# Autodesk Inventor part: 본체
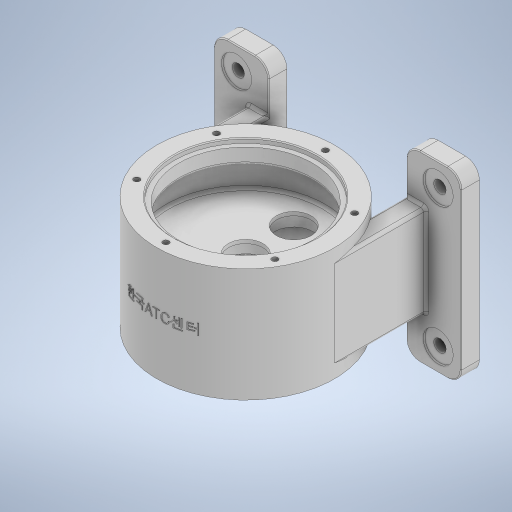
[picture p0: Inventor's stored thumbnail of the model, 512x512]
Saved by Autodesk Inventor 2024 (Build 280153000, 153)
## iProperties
Created: 2025-12
Part Number: 본체
Material: 일반
Document SubType Name: Modeling
Designer: Edu07
Density: 1 g/cm^3
Appearance: 기본값
Author: Edu07
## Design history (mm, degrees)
sketch "스케치3"
  geometry: L1 (135, 85)-(135, -85); L2 (-135, -85)-(-135, 85); L3 (-75, -85)-(-75, 85); L4 (75, 85)-(75, -85); L5 (-120, 100)-(-90, 100); L6 (90, 100)-(120, 100); L7 (120, -100)-(90, -100); L8 (-90, -100)-(-120, -100); C1 r 6.75 at (-110, 75); C2 r 6.75 at (110, 75); C3 r 6.75 at (110, -75); C4 r 6.75 at (-110, -75); A1 r 15 centre (-120, 85) between (-120, 100) and (-135, 85); A2 r 15 centre (-90, 85) between (-75, 85) and (-90, 100); A3 r 15 centre (-90, -85) between (-90, -100) and (-75, -85); A4 r 15 centre (-120, -85) between (-135, -85) and (-120, -100); A5 r 15 centre (90, 85) between (90, 100) and (75, 85); A6 r 15 centre (120, 85) between (135, 85) and (120, 100); A7 r 15 centre (120, -85) between (120, -100) and (135, -85); A8 r 15 centre (90, -85) between (75, -85) and (90, -100); 3 further points
  constraints: 16 end point, 16 point on circle, 16 tangent, 12 centre point, 7 equal radius, 7 parallel, 4 point on line, 2 perpendicular
  dimensions: "d4" = 200 distance of point (135, 100) point (135, -100); "d5" = 60 distance between parallel lines of L2 L3; "d6" = 60 distance between parallel lines of L1 L4; "d7" = 15 radius of A1; "d10" = 13.5 diameter of C1; "d11" = 13.5 diameter of C2; "d12" = 13.5 diameter of C3; "d13" = 13.5 diameter of C4
extrude "돌출3" new body sketch "스케치3" distance "d16" = 20; taper "d17" = 0 deg
sketch "스케치4"
  geometry: C1 r 6.75 at (-110, 75) reference; C2 r 16.5 at (-110, 75); C3 r 6.75 at (-110, -75) reference; C4 r 16.5 at (-110, -75); C5 r 6.75 at (110, 75) reference; C6 r 16.5 at (110, 75); C7 r 6.75 at (110, -75) reference; C8 r 16.5 at (110, -75); 1 further point
  constraints: 4 centre point, 4 coincident
  dimensions: "d18" = 33 diameter of C2; "d19" = 33 diameter of C4; "d20" = 33 diameter of C6; "d21" = 33 diameter of C8
extrude "돌출4" cut sketch "스케치4" distance "d22" = 2; taper "d23" = 0 deg
sketch "스케치6"
  geometry: L1 (0, 0)-(0, 120); C1 r 97 at (0, 120)
  constraints: 2 end point, 1 centre point, 1 coincident, 1 vertical
  dimensions: "d24" = 120 distance of L1.start L1.end; "d25" = 194 diameter of C1
extrude "돌출5" join sketch "스케치6" stored distance "d26" = 124; taper "d27" = 0 deg
node "작업 평면2"
sketch "스케치7"
  geometry: 2 further points
  constraints: 2 coincident, 1 other
feature "엠보싱1" sketch "스케치7" dims "d4" = 200, "d5" = 60, "d6" = 60, "d7" = 15, "d29" = 0.5, "d30" = 0
sketch "스케치9"
  geometry: L1 (75, 20)-(75, 58.486) reference; L2 (75, 0)-(75, 20) reference; L3 (75, 20)-(97, 20); L4 (120, 20)-(90, 20) reference; L5 (97, 20)-(97, 120); L6 (75, 20)-(75, 58.486); A1 r 97 centre (0, 120) between (75, 58.486) and (97, 120) reference; A2 r 97 centre (0, 120) between (75, 58.486) and (97, 120); 1 further point
  constraints: 6 end point, 3 point on circle, 1 centre point, 1 collinear, 1 concentric, 1 perpendicular, 1 point on line
  dimensions: "d38" = 22 distance of L1.start L3.end
extrude "돌출6" join sketch "스케치9" stored distance "d39" = 100; taper "d40" = 0 deg
sketch "스케치10"
  geometry: C1 r 78 at (0, 0); 1 further point
  constraints: 1 centre point
  dimensions: "d43" = 156 diameter of C1
extrude "돌출7" cut sketch "스케치10" distance "d44" = 5; taper "d45" = 0 deg
sketch "스케치11"
  geometry: C1 r 78 at (0, 0) reference; C2 r 73 at (0, 0); 1 further point
  constraints: 1 centre point, 1 coincident
  dimensions: "d46" = 146 diameter of C2
  node "투영된 루프2"
sketch "스케치12"
  geometry: 1 further point
extrude "돌출8" cut sketch "스케치11" distance "d47" = 17; taper "d48" = 0 deg
sketch "스케치13"
  geometry: C1 r 73 at (0, 0) reference; C2 r 87 at (0, 0); 1 further point
  constraints: 1 centre point, 1 coincident
  dimensions: "d49" = 174 diameter of C2
extrude "돌출9" cut sketch "스케치13" distance "d50" = 32; taper "d51" = 0 deg
sketch "스케치14"
  geometry: C1 r 73 at (0, 0) reference; C2 r 21 at (0, 0); 1 further point
  constraints: 1 centre point, 1 coincident
  dimensions: "d52" = 42 diameter of C2
extrude "돌출10" cut sketch "스케치14" distance "d53" = 12; taper "d54" = 0 deg
sketch "스케치15"
  geometry: C1 r 19 at (0, 0); 1 further point
  constraints: 1 centre point
  dimensions: "d55" = 38 diameter of C1
extrude "돌출11" cut sketch "스케치15" distance "d56" = 12; taper "d57" = 0 deg
sketch "스케치16" dims "d58" = 174
  geometry: 3 further points
  constraints: 1 vertical alignment, 2 other
hole "구멍1" sketch "스케치16" at (0, 87) diameter "d59" = 6.647; stored, may be unused: countersink angle "d63" = 82 deg, drill point angle "d65" = 118 deg; dims "d60" = 16, "d61" = 3.023, "d62" = 2, "d64" = 18
sketch "스케치19"
  geometry: L1 (75, 8)-(36.6, 30.17); L2 (75, 58.486)-(75, 20) reference; L3 (75, 8)-(75, 58.486); C1 r 3.324 at (75.344, 163.5) reference; C2 r 3.324 at (75.344, 76.5) reference; C3 r 3.324 at (0, 33) reference; C4 r 3.324 at (-75.344, 76.5) reference; C5 r 3.324 at (-75.344, 163.5) reference; C6 r 3.324 at (0, 207) reference; C7 r 78 at (0, 120) reference; A1 r 97 centre (0, 120) between (75, 58.486) and (36.6, 30.17) reference; 2 further points
  constraints: 4 end point, 2 point on circle
feature "리브2" sketch "스케치19" dims "d78" = 1, "d79" = 12, "d80" = 0, "d81" = 0, "d82" = 1, "d83" = 1
chamfer "모따기1" distance "d84" = 1; stored, may be unused: second distance "d85" = 2, angle "d86" = 30 deg
fillet "모깎기1" dims "d87" = 3
fillet "모깎기2" dims "d88" = 3
fillet "모깎기3" dims "d89" = 3
fillet "모깎기4" dims "d90" = 3
sketch "스케치20"
  geometry: 1 further point
sketch "스케치21"
  geometry: L1 (-57, 47)-(-57, 193) reference; L2 (-57, 193)-(-40, 193); L3 (-57, 193)-(-8, 193) reference; L4 (-40, 193)-(-8, 193); L5 (-8, 99)-(-8, 141) reference; L6 (-8, 207)-(-40, 207); L7 (-40, 207)-(-40, 193); L8 (-8, 120)-(-43.798, 120); L9 (-47, 120)-(47, 120) reference; L10 (-8, 207)-(-8, 193); 1 further point
  constraints: 12 end point, 3 point on line, 1 midpoint, 1 vertical
  dimensions: "d93" = 17 distance of L1.end L2.end; "d94" = 32 distance of L2.end L4.end; "d95" = 87 distance of L8.start L6.start; "d96" = 32 distance of L6.start L6.end
revolve "회전1" sketch "스케치21" stored, may be unused: angle "d97" = 90 deg
sketch "스케치22"
  geometry: 1 further point
fillet "모깎기5" dims "d98" = 3
fillet "모깎기6" dims "d99" = 3
chamfer "모따기2" distance "d100" = 1; stored, may be unused: second distance "d101" = 2, angle "d102" = 30 deg
chamfer "모따기3" distance "d103" = 1; stored, may be unused: second distance "d104" = 2, angle "d105" = 30 deg
sketch "스케치25"
  geometry: L1 (0, 0)-(0, 52.5); C1 r 19 at (0, 52.5); 1 further point
  constraints: 2 end point, 1 centre point, 1 coincident, 1 vertical
  dimensions: "d108" = 52.5 distance of L1.start L1.end; "d109" = 38 diameter of C1
extrude "돌출12" cut sketch "스케치25" distance "d110" = 4; taper "d111" = 0 deg
sketch "스케치26"
  geometry: C1 r 21 at (0, 0); 1 further point
  constraints: 1 centre point
  dimensions: "d112" = 42 diameter of C1
extrude "돌출13" cut sketch "스케치26" stored distance "d113" = 4; taper "d114" = 0 deg
sketch "스케치27"
  geometry: L1 (-23.383, -39)-(-35.599, -60.16); L2 (-39.648, -67.172)-(-40.933, -69.398); L3 (23.383, -39)-(35.599, -60.16); C1 r 21 at (0, -52.5); A1 r 27 centre (0, -52.5) between (23.383, -39) and (-23.383, -39); A2 r 3 centre (-38.197, -58.66) between (-39.834, -61.174) and (-35.599, -60.16); A3 r 3 centre (38.197, -58.66) between (35.599, -60.16) and (39.834, -61.174); A4 r 73 centre (0, 0) between (-39.834, -61.174) and (39.834, -61.174); 8 further points
  constraints: 9 point on circle, 6 end point, 5 centre point, 4 tangent, 3 point on line, 2 coincident
  dimensions: "d115" = 42 diameter of C1; "d119" = 54 diameter of A1; "d124" = 3 radius of A2 (derived); "d125" = 3 radius of A3 (derived)
extrude "돌출14" join sketch "스케치27" distance "d126" = 17; taper "d127" = 0 deg
fillet "모깎기7" dims "d128" = 3
node "솔리드3"
mirror "미러1"
mirror "미러2"
pattern_circular "원형 패턴1" dims angle "d67" = 360 deg
mirror "미러3"
mirror "미러4"
mirror "미러5"
node "투영된 루프3"
node "투영된 루프4"
other parameters: "d28" = 263.25, "d120" = 150 deg
